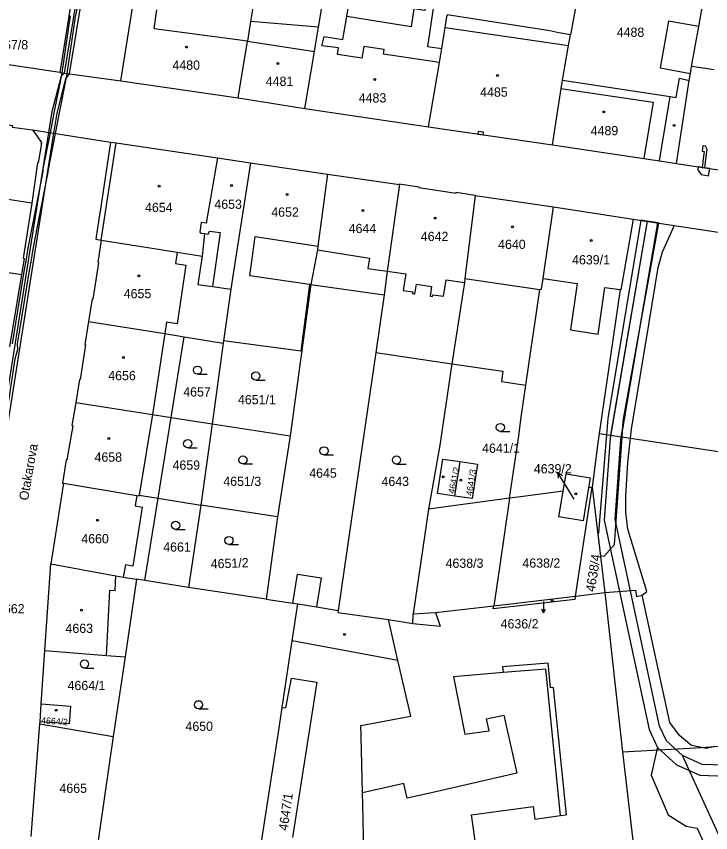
# Model space of a CAD drawing. Extents: x -756746 to -753363, y -1166406 to -1161727.
# Drawn here: x -755379 to -755251.5, y -1166014.7 to -1165864.8 of the extents above; entities that cross this region are included whole.
import ezdxf

# ---------------------------------------------------------------- set-up
doc = ezdxf.new("R2010")
doc.units = 0
for name, color, linetype in [('Hranice parcel', 7, 'Continuous'), ('Parcelní čísla', 7, 'Continuous'), ('Pop  PČ popisy', 7, 'Continuous'), ('Vnitřní kresba', 7, 'Continuous'), ('Věcná břemena k části', 7, 'Continuous'), ('Značky budov', 7, 'Continuous'), ('Značky kultur', 7, 'Continuous')]:
    doc.layers.add(name, color=color, linetype=linetype)

msp = doc.modelspace()

# ---------------------------------------------------------------- linework, layer by layer
at = {"layer": 'Hranice parcel'}
for p, q in [((-755333.64, -1165850.7), (-755336.01, -1165865.74)), ((-755323.54, -1165866.79), (-755322.25, -1165859.17)), ((-755359.86, -1165876.65), (-755357.62, -1165862.89)), ((-755336.01, -1165865.74), (-755336.58, -1165869.38)), ((-755323.54, -1165866.79), (-755336.01, -1165865.74)), ((-755338.26, -1165879.79), (-755336.58, -1165869.38)), ((-755371.06, -1165875.11), (-755390.26, -1165872.27)), ((-755371.06, -1165875.11), (-755359.86, -1165876.65)), ((-755359.86, -1165876.65), (-755338.26, -1165879.79)), ((-755257.81, -1165891.82), (-755255.48, -1165876.6)), ((-755338.26, -1165879.79), (-755326.03, -1165881.71)), ((-755326.03, -1165881.71), (-755303.36, -1165885.1)), ((-755376.04, -1165885.67), (-755361.71, -1165887.89)), ((-755303.36, -1165885.1), (-755280.55, -1165888.41)), ((-755342.06, -1165890.8), (-755336.05, -1165891.68)), ((-755336.05, -1165891.68), (-755321.86, -1165893.79)), ((-755321.86, -1165893.79), (-755308.67, -1165895.66)), ((-755294.79, -1165897.7), (-755280.39, -1165899.79)), ((-755280.39, -1165899.79), (-755265.76, -1165902.04)), ((-755324.96, -1165914.06), (-755328.74, -1165941.83)), ((-755324.96, -1165914.06), (-755311.47, -1165915.98)), ((-755339.65, -1165914.88), (-755340.98, -1165924.42)), ((-755311.47, -1165915.98), (-755313, -1165926.52)), ((-755350.58, -1165938.48), (-755348.19, -1165923.64)), ((-755348.19, -1165923.64), (-755341.04, -1165924.83)), ((-755340.98, -1165924.42), (-755341.04, -1165924.83)), ((-755341.04, -1165924.83), (-755343.04, -1165939.67)), ((-755313, -1165926.52), (-755299.07, -1165928.63)), ((-755353.01, -1165953.29), (-755350.58, -1165938.48)), ((-755350.58, -1165938.48), (-755343.04, -1165939.67)), ((-755343.04, -1165939.67), (-755345.12, -1165954.56)), ((-755343.04, -1165939.67), (-755328.74, -1165941.83)), ((-755328.74, -1165941.83), (-755331.04, -1165956.71)), ((-755298.51, -1165952.93), (-755297.54, -1165946.58)), ((-755370.37, -1165950.57), (-755372.69, -1165965.37)), ((-755276.37, -1165971.3), (-755273.28, -1165951.31)), ((-755273.28, -1165951.31), (-755273.93, -1165951.4)), ((-755273.28, -1165951.31), (-755270.93, -1165970.66)), ((-755355.41, -1165968.42), (-755353.01, -1165953.29)), ((-755353.01, -1165953.29), (-755345.12, -1165954.56)), ((-755345.12, -1165954.56), (-755347.4, -1165969.71)), ((-755331.04, -1165956.71), (-755345.12, -1165954.56)), ((-755288.46, -1165953.33), (-755303.33, -1165955.3)), ((-755303.33, -1165955.3), (-755306.13, -1165974.57)), ((-755331.04, -1165956.71), (-755333.14, -1165971.84)), ((-755373.77, -1165981.29), (-755372.69, -1165965.37)), ((-755356.97, -1165968.21), (-755359.07, -1165982.44)), ((-755355.41, -1165968.42), (-755356.97, -1165968.21)), ((-755347.4, -1165969.71), (-755355.41, -1165968.42)), ((-755333.14, -1165971.84), (-755347.4, -1165969.71)), ((-755276.37, -1165971.3), (-755270.93, -1165970.66)), ((-755270.93, -1165970.66), (-755267.71, -1165999.92)), ((-755276.46, -1165971.89), (-755291.44, -1165973.65)), ((-755291.35, -1165973.06), (-755276.37, -1165971.3)), ((-755276.37, -1165971.3), (-755276.46, -1165971.89)), ((-755291.44, -1165973.65), (-755291.35, -1165973.06)), ((-755374.44, -1165991.11), (-755373.77, -1165981.29)), ((-755359.07, -1165982.44), (-755361.23, -1165997.07)), ((-755374.67, -1165994.37), (-755374.44, -1165991.11)), ((-755376.29, -1166015.44), (-755374.69, -1165994.77)), ((-755374.69, -1165994.77), (-755374.67, -1165994.37)), ((-755374.69, -1165994.77), (-755361.23, -1165997.07)), ((-755267.71, -1165999.92), (-755264.63, -1166026.3))]:
    msp.add_line(p, q, dxfattribs=at)
for points in [[(-755298.59, -1165856.2), (-755301.27, -1165855.58), (-755301.84, -1165858.89), (-755302.48, -1165858.78), (-755303.01, -1165861.27), (-755303.67, -1165861.19), (-755303.83, -1165862.7), (-755304, -1165863.75), (-755306.02, -1165863.42), (-755306.55, -1165866.72), (-755318.35, -1165864.82), (-755317.54, -1165859.92), (-755322.25, -1165859.17)], [(-755275.08, -1165855.46), (-755276.29, -1165862.87), (-755277.26, -1165868.19)], [(-755368.38, -1165858.31), (-755369.41, -1165864.76), (-755371.06, -1165875.11)], [(-755255.48, -1165876.6), (-755255.24, -1165875.27), (-755255.01, -1165873.98), (-755253.7, -1165866.66), (-755252.4, -1165859.39)], [(-755336.58, -1165869.38), (-755353.72, -1165867.07), (-755353.25, -1165863.62)], [(-755303.36, -1165885.1), (-755301.3, -1165873.3), (-755300.89, -1165870.7), (-755300.29, -1165866.87), (-755299.91, -1165864.49)], [(-755277.26, -1165868.19), (-755279.38, -1165867.8), (-755281.03, -1165867.48), (-755299.91, -1165864.49)], [(-755326.03, -1165881.71), (-755324.3, -1165871.28), (-755324.11, -1165870.11), (-755323.54, -1165866.79)], [(-755278.71, -1165876.54), (-755277.6, -1165870.15), (-755277.26, -1165868.19)], [(-755280.55, -1165888.41), (-755278.97, -1165878.03), (-755278.71, -1165876.54)], [(-755278.71, -1165876.54), (-755258.97, -1165879.54), (-755257.86, -1165879.73), (-755257.25, -1165876.15), (-755255.48, -1165876.6)], [(-755388.14, -1165883.94), (-755384.43, -1165884.47), (-755384.38, -1165884.17), (-755379.73, -1165884.84), (-755379.78, -1165885.14), (-755376.04, -1165885.67)], [(-755376.04, -1165885.67), (-755374.39, -1165887.99), (-755374.55, -1165888.15), (-755374.42, -1165888.17), (-755374.99, -1165891.71), (-755375.14, -1165891.68), (-755376.2, -1165899.14)], [(-755361.71, -1165887.89), (-755363.52, -1165899.78), (-755364.11, -1165903.66), (-755364.42, -1165905.71), (-755363.44, -1165905.89)], [(-755361.71, -1165887.89), (-755360.68, -1165888.04), (-755342.06, -1165890.8)], [(-755280.55, -1165888.41), (-755263.78, -1165890.92), (-755260.9, -1165891.35), (-755257.81, -1165891.82)], [(-755342.06, -1165890.8), (-755344.19, -1165902.8), (-755345.11, -1165902.65), (-755345.35, -1165904.43), (-755345.07, -1165904.63), (-755344.47, -1165904.71), (-755344.89, -1165908.84)], [(-755336.05, -1165891.68), (-755339.22, -1165912.07), (-755339.65, -1165914.88)], [(-755257.81, -1165891.82), (-755254.21, -1165892.37), (-755234.75, -1165895.27)], [(-755321.86, -1165893.79), (-755323.65, -1165907.02), (-755323.75, -1165907.71), (-755324.96, -1165914.06)], [(-755308.67, -1165895.66), (-755310.9, -1165911.61), (-755311.47, -1165915.98)], [(-755308.67, -1165895.66), (-755308.66, -1165895.59), (-755305.1, -1165896.11), (-755305.12, -1165896.23), (-755298.26, -1165897.26), (-755298.24, -1165897.12), (-755294.78, -1165897.63), (-755294.79, -1165897.7)], [(-755376.2, -1165899.14), (-755384.18, -1165897.9), (-755387.74, -1165897.34), (-755388.9, -1165897.16), (-755390.02, -1165896.98)], [(-755376.2, -1165899.14), (-755377.75, -1165909.24), (-755377.6, -1165909.27), (-755378.06, -1165912.25)], [(-755294.79, -1165897.7), (-755296.65, -1165912.98), (-755296.74, -1165913.69), (-755299.07, -1165928.63)], [(-755285.47, -1165932.53), (-755284.49, -1165925.78), (-755283.64, -1165920.07), (-755282.88, -1165914.94), (-755282.59, -1165914.93), (-755282.3, -1165912.94), (-755280.39, -1165899.79)], [(-755265.76, -1165902.04), (-755268.04, -1165915.01), (-755268.14, -1165914.99), (-755271.99, -1165941.43)], [(-755265.76, -1165902.04), (-755258.2, -1165903.19), (-755226.15, -1165908.07)], [(-755363.44, -1165905.89), (-755364.08, -1165910.03), (-755363.96, -1165910.05), (-755365, -1165916.73), (-755365.13, -1165916.71), (-755365.78, -1165920.87)], [(-755363.44, -1165905.89), (-755352.55, -1165907.63), (-755349.49, -1165908.11), (-755344.89, -1165908.84)], [(-755378.06, -1165912.25), (-755391.46, -1165910.18), (-755397.87, -1165909.19)], [(-755344.89, -1165908.84), (-755345.68, -1165914.04), (-755342.99, -1165914.41), (-755339.65, -1165914.88)], [(-755378.06, -1165912.25), (-755380.27, -1165925.46), (-755380.4, -1165925.44)], [(-755324.96, -1165914.06), (-755325.18, -1165914.03), (-755326.81, -1165926.29), (-755340.98, -1165924.42)], [(-755365.78, -1165920.87), (-755366.45, -1165925.11), (-755366.31, -1165925.13), (-755367.31, -1165931.5), (-755367.45, -1165931.48), (-755368.11, -1165935.7)], [(-755365.78, -1165920.87), (-755351.76, -1165923.04), (-755348.19, -1165923.64)], [(-755313, -1165926.52), (-755315.26, -1165942.02), (-755317.58, -1165957.88), (-755319.95, -1165973.95)], [(-755299.07, -1165928.63), (-755301.24, -1165943.59), (-755303.33, -1165955.3)], [(-755299.07, -1165928.63), (-755289.66, -1165930), (-755289.94, -1165931.86), (-755285.47, -1165932.53)], [(-755288.46, -1165953.33), (-755286.83, -1165942.28), (-755286.3, -1165938.44), (-755285.47, -1165932.53)], [(-755368.11, -1165935.7), (-755368.82, -1165939.97), (-755368.67, -1165940), (-755369.73, -1165946.29), (-755369.86, -1165946.27), (-755370.57, -1165950.54), (-755370.37, -1165950.57)], [(-755368.11, -1165935.7), (-755354.01, -1165937.94), (-755350.58, -1165938.48)], [(-755271.99, -1165941.43), (-755272.23, -1165943.13), (-755273.28, -1165951.31)], [(-755271.99, -1165941.43), (-755266.24, -1165942.3), (-755231.88, -1165947.5)], [(-755298.51, -1165952.93), (-755301.71, -1165952.46), (-755300.72, -1165946.12), (-755297.54, -1165946.58)], [(-755297.54, -1165946.58), (-755294.36, -1165947.05), (-755295.31, -1165953.39), (-755298.51, -1165952.93)], [(-755278.61, -1165952.02), (-755278.07, -1165948.83), (-755273.62, -1165949.54), (-755273.93, -1165951.4)], [(-755370.37, -1165950.57), (-755356.91, -1165952.82), (-755356.47, -1165952.89), (-755356.45, -1165952.74), (-755353.01, -1165953.29)], [(-755273.93, -1165951.4), (-755274.94, -1165957.44), (-755279.4, -1165956.72), (-755278.61, -1165952.02)], [(-755278.61, -1165952.02), (-755286.45, -1165953.06), (-755288.46, -1165953.33)], [(-755288.46, -1165953.33), (-755290.32, -1165966.05), (-755291.35, -1165973.06)], [(-755372.69, -1165965.37), (-755360.76, -1165967.57), (-755359.38, -1165967.82), (-755356.97, -1165968.21)], [(-755333.14, -1165971.84), (-755328.28, -1165972.57), (-755327.36, -1165972.71)], [(-755335.36, -1166025.81), (-755334.11, -1166017.2), (-755332.76, -1166008.51), (-755330.85, -1165995.94), (-755330.23, -1165991.73), (-755328.39, -1165979.53), (-755327.36, -1165972.71)], [(-755327.36, -1165972.71), (-755323.93, -1165973.29), (-755319.95, -1165973.95)], [(-755319.95, -1165973.95), (-755320, -1165974.31), (-755310.67, -1165975.6)], [(-755306.13, -1165974.57), (-755302.05, -1165974.32), (-755291.35, -1165973.06)], [(-755315, -1166027.54), (-755315.21, -1166018.6), (-755315.42, -1166009.49), (-755315.47, -1166007.43), (-755315.72, -1165997.02), (-755315.75, -1165995.05), (-755306.6, -1165993.33), (-755308.94, -1165983.12), (-755310.67, -1165975.6)], [(-755310.67, -1165975.6), (-755306.22, -1165976.34), (-755306.13, -1165974.57)], [(-755373.77, -1165981.29), (-755362.46, -1165982.18), (-755359.07, -1165982.44)], [(-755374.44, -1165991.11), (-755369.07, -1165991.51), (-755369.3, -1165994.77), (-755374.67, -1165994.37)], [(-755361.23, -1165997.07), (-755362.04, -1166002.59), (-755364.7, -1166020.81)], [(-755267.71, -1165999.92), (-755253.23, -1165999.08), (-755250.82, -1165998.94), (-755233.62, -1165997.95)]]:
    msp.add_lwpolyline(points, dxfattribs=at)
at = {"layer": 'Pop  PČ popisy'}
for p, q in [((-755278.06, -1165951.08), (-755279.65, -1165948.53)), ((-755279.65, -1165948.53), (-755278.7, -1165949.12)), ((-755279.65, -1165948.53), (-755279.54, -1165949.65)), ((-755276.57, -1165953.49), (-755278.06, -1165951.08)), ((-755282.2, -1165972.27), (-755282.2, -1165974.37)), ((-755282.2, -1165974.37), (-755282.55, -1165973.67)), ((-755282.2, -1165974.37), (-755281.85, -1165973.67))]:
    msp.add_line(p, q, dxfattribs=at)
at = {"layer": 'Vnitřní kresba'}
for p, q in [((-755302.39, -1165862.93), (-755303.54, -1165870.34)), ((-755319.04, -1165869.03), (-755318.35, -1165864.82)), ((-755259.26, -1165865.66), (-755260.79, -1165874.27)), ((-755253.7, -1165866.66), (-755259.26, -1165865.66)), ((-755300.29, -1165866.87), (-755277.6, -1165870.15)), ((-755322.9, -1165870.24), (-755322.49, -1165868.47)), ((-755322.49, -1165868.47), (-755319.04, -1165869.03)), ((-755336.58, -1165869.38), (-755324.3, -1165871.28)), ((-755319.85, -1165870.57), (-755322.9, -1165870.24)), ((-755320.04, -1165871.83), (-755319.85, -1165870.57)), ((-755315.23, -1165870.34), (-755315.55, -1165872.48)), ((-755311.47, -1165870.9), (-755315.23, -1165870.34)), ((-755303.54, -1165870.34), (-755300.89, -1165870.7)), ((-755315.55, -1165872.48), (-755320.04, -1165871.83)), ((-755311.6, -1165871.77), (-755311.47, -1165870.9)), ((-755301.3, -1165873.3), (-755311.6, -1165871.77)), ((-755260.79, -1165874.27), (-755255.24, -1165875.27)), ((-755250.86, -1165874.61), (-755255.01, -1165873.98)), ((-755278.97, -1165878.03), (-755276.99, -1165878.33)), ((-755276.99, -1165878.33), (-755262.09, -1165880.57)), ((-755260.9, -1165891.35), (-755258.97, -1165879.54)), ((-755262.09, -1165880.57), (-755263.78, -1165890.92)), ((-755363.44, -1165905.89), (-755360.68, -1165888.04)), ((-755260.38, -1165908.07), (-755258.37, -1165903.58)), ((-755258.37, -1165903.58), (-755258.2, -1165903.19)), ((-755344.47, -1165904.71), (-755343.82, -1165904.79)), ((-755343.82, -1165904.79), (-755343.55, -1165904.25)), ((-755343.55, -1165904.25), (-755341.6, -1165904.53)), ((-755341.6, -1165904.53), (-755342.99, -1165914.41)), ((-755336.17, -1165912.47), (-755335.14, -1165905.25)), ((-755335.14, -1165905.25), (-755323.65, -1165907.02)), ((-755349.49, -1165908.11), (-755349.81, -1165910.18)), ((-755323.75, -1165907.71), (-755314.19, -1165909.21)), ((-755261.13, -1165910.91), (-755260.38, -1165908.07)), ((-755314.19, -1165909.21), (-755314.49, -1165911.11)), ((-755349.81, -1165910.18), (-755347.89, -1165910.47)), ((-755347.89, -1165910.47), (-755349.52, -1165921.26)), ((-755314.49, -1165911.11), (-755310.9, -1165911.61)), ((-755262.88, -1165921.38), (-755261.13, -1165910.91)), ((-755325.18, -1165914.03), (-755336.17, -1165912.47)), ((-755310.9, -1165911.61), (-755307.52, -1165912.1)), ((-755307.52, -1165912.1), (-755307.96, -1165915.13)), ((-755305.83, -1165915.8), (-755305.57, -1165914.01)), ((-755305.57, -1165914.01), (-755302.78, -1165914.42)), ((-755300.56, -1165916.21), (-755300.12, -1165913.18)), ((-755300.12, -1165913.18), (-755296.74, -1165913.69)), ((-755296.65, -1165912.98), (-755282.88, -1165914.94)), ((-755282.3, -1165912.94), (-755276.03, -1165913.87)), ((-755276.03, -1165913.87), (-755277.28, -1165922.4)), ((-755307.96, -1165915.13), (-755306.22, -1165915.39)), ((-755306.22, -1165915.39), (-755306.27, -1165915.73)), ((-755302.78, -1165914.42), (-755303.04, -1165916.2)), ((-755272.18, -1165923.15), (-755270.93, -1165914.61)), ((-755270.93, -1165914.61), (-755268.14, -1165914.99)), ((-755306.27, -1165915.73), (-755305.83, -1165915.8)), ((-755303.04, -1165916.2), (-755302.6, -1165916.27)), ((-755302.6, -1165916.27), (-755302.55, -1165915.92)), ((-755302.55, -1165915.92), (-755300.56, -1165916.21)), ((-755351.45, -1165920.97), (-755351.76, -1165923.04)), ((-755349.52, -1165921.26), (-755351.45, -1165920.97)), ((-755266.07, -1165940.65), (-755262.88, -1165921.38)), ((-755351.76, -1165923.04), (-755354.01, -1165937.94)), ((-755277.28, -1165922.4), (-755272.18, -1165923.15)), ((-755354.01, -1165937.94), (-755356.45, -1165952.74)), ((-755266.24, -1165942.3), (-755266.07, -1165940.65)), ((-755266.71, -1165946.76), (-755266.24, -1165942.3)), ((-755267.11, -1165952.94), (-755266.71, -1165946.76)), ((-755356.91, -1165952.82), (-755357.23, -1165954.74)), ((-755267.07, -1165955.89), (-755267.11, -1165952.94)), ((-755355.89, -1165954.96), (-755357.65, -1165965.8)), ((-755357.23, -1165954.74), (-755355.89, -1165954.96)), ((-755266.72, -1165958.99), (-755267.07, -1165955.89)), ((-755263.22, -1165970.46), (-755266.72, -1165958.99)), ((-755359.01, -1165965.57), (-755359.38, -1165967.82)), ((-755357.65, -1165965.8), (-755359.01, -1165965.57)), ((-755360.9, -1165970.27), (-755360.76, -1165967.57)), ((-755328.28, -1165972.57), (-755327.4, -1165967.27)), ((-755327.4, -1165967.27), (-755323.04, -1165967.95)), ((-755323.04, -1165967.95), (-755323.93, -1165973.29)), ((-755362.46, -1165982.18), (-755361.85, -1165970.22)), ((-755361.85, -1165970.22), (-755360.9, -1165970.27)), ((-755270.93, -1165970.66), (-755265.35, -1165970.2)), ((-755265.35, -1165970.2), (-755265.15, -1165971.35)), ((-755265.15, -1165971.35), (-755264.08, -1165971.13)), ((-755264.08, -1165971.13), (-755263.22, -1165970.46)), ((-755259.01, -1165994.54), (-755264.08, -1165971.13)), ((-755302.05, -1165974.32), (-755301.17, -1165976.81)), ((-755306.22, -1165976.34), (-755301.17, -1165976.81)), ((-755308.94, -1165983.12), (-755328.39, -1165979.53)), ((-755281.37, -1165983.59), (-755289.74, -1165984.31)), ((-755289.74, -1165984.31), (-755289.65, -1165985.35)), ((-755280.92, -1165988.12), (-755281.37, -1165983.59)), ((-755289.65, -1165985.35), (-755298.77, -1165986.11)), ((-755298.77, -1165986.11), (-755296.65, -1165996.65)), ((-755281.8, -1165984.69), (-755289.65, -1165985.35)), ((-755279.12, -1166011.6), (-755281.8, -1165984.69)), ((-755329.54, -1165991.83), (-755328.51, -1165986.38)), ((-755328.51, -1165986.38), (-755323.87, -1165987.08)), ((-755323.87, -1165987.08), (-755328.33, -1166015.66)), ((-755280.44, -1165988.07), (-755280.92, -1165988.12)), ((-755280.44, -1165988.07), (-755278.07, -1166011.46)), ((-755330.23, -1165991.73), (-755329.54, -1165991.83)), ((-755292.67, -1165993.84), (-755289.48, -1165993.15)), ((-755289.48, -1165993.15), (-755289, -1165995.36)), ((-755292.18, -1165996.06), (-755292.67, -1165993.84)), ((-755257.27, -1165996.88), (-755259.01, -1165994.54)), ((-755296.65, -1165996.65), (-755292.18, -1165996.06)), ((-755289, -1165995.36), (-755287.13, -1166003.83)), ((-755255.01, -1165998.74), (-755257.27, -1165996.88)), ((-755253.23, -1165999.08), (-755255.01, -1165998.74)), ((-755252.26, -1165999.27), (-755253.23, -1165999.08)), ((-755250.82, -1165998.94), (-755252.26, -1165999.27)), ((-755287.13, -1166003.83), (-755303.34, -1166007.54)), ((-755307.86, -1166005.71), (-755315.47, -1166007.43)), ((-755307.24, -1166008.42), (-755307.86, -1166005.71)), ((-755303.34, -1166007.54), (-755307.24, -1166008.42)), ((-755295.44, -1166011.5), (-755284.09, -1166009.96)), ((-755284.09, -1166009.96), (-755283.78, -1166012.24)), ((-755294.57, -1166017.52), (-755295.44, -1166011.5)), ((-755283.78, -1166012.24), (-755279.12, -1166011.6)), ((-755279.12, -1166011.6), (-755278.07, -1166011.46))]:
    msp.add_line(p, q, dxfattribs=at)
at = {"layer": 'Věcná břemena k části'}
for points in [[(-755363.63, -1165835.25), (-755370.22, -1165875.23), (-755370.82, -1165875.79), (-755372.53, -1165882.36), (-755373.13, -1165886.12), (-755385.09, -1165961.43)], [(-755384.09, -1165961.55), (-755372.14, -1165886.27), (-755371.55, -1165882.56), (-755369.92, -1165876.29), (-755369.26, -1165875.35), (-755362.57, -1165834.95)], [(-755385.7, -1165976), (-755385.24, -1165970.06), (-755385.09, -1165967.62), (-755384.74, -1165963.55), (-755384.22, -1165958.86), (-755383.1, -1165952.19), (-755382.24, -1165946.62), (-755380.28, -1165934.63), (-755379.25, -1165927.68), (-755378.78, -1165925.92), (-755378.82, -1165925), (-755376.67, -1165911.82), (-755376.32, -1165909.89), (-755375.93, -1165907.57), (-755373.96, -1165897.48), (-755373.19, -1165893.41), (-755373.15, -1165892.92), (-755371.85, -1165886.32), (-755371.15, -1165882.8), (-755369.79, -1165876), (-755369.69, -1165875.3), (-755368.15, -1165864.9), (-755367.31, -1165860.7)], [(-755369.13, -1165864.72), (-755370.67, -1165875.16), (-755370.77, -1165875.82), (-755372.13, -1165882.6), (-755372.84, -1165886.17), (-755374.15, -1165892.78), (-755374.19, -1165893.27), (-755374.9, -1165897.12), (-755376.91, -1165907.39), (-755377.3, -1165909.71), (-755377.65, -1165911.66), (-755379.82, -1165924.94)], [(-755249.05, -1166002.33), (-755253.05, -1166002.21), (-755256.71, -1166000.59), (-755259.65, -1165997.88), (-755260.89, -1165995.17), (-755269.06, -1165957.22), (-755267.99, -1165942.54), (-755261.22, -1165902.73), (-755263.19, -1165902.43), (-755269.98, -1165942.3), (-755271.07, -1165957.36), (-755262.8, -1165995.81), (-755261.3, -1165999.08), (-755257.82, -1166002.28), (-755253.5, -1166004.19), (-755248.65, -1166004.34)]]:
    msp.add_lwpolyline(points, dxfattribs=at)
for points in [[(-755294.29, -1165886.42), (-755293.31, -1165886.56), (-755293.23, -1165886.08), (-755294.21, -1165885.92)], [(-755252.47, -1165888.63), (-755252.96, -1165888.56), (-755253.11, -1165889.55), (-755252.73, -1165889.6), (-755252.86, -1165890.5), (-755253.09, -1165892.54), (-755252.6, -1165892.61), (-755252.36, -1165890.56), (-755252.17, -1165889.23)], [(-755252.6, -1165892.61), (-755253.09, -1165892.54), (-755253.83, -1165892.43), (-755253.9, -1165893), (-755253.26, -1165893.84), (-755251.92, -1165894.07), (-755251.69, -1165892.75)], [(-755272.1, -1165959.65), (-755272.24, -1165959.84), (-755271.75, -1165963.93), (-755271.01, -1165963.87), (-755269.17, -1165961.81), (-755267.79, -1165942.07), (-755267.58, -1165939.08), (-755261.02, -1165902.76), (-755264.37, -1165902.25), (-755270.41, -1165938.65), (-755270.65, -1165941.63)], [(-755267.91, -1165942.05), (-755261.22, -1165902.73), (-755263.19, -1165902.43), (-755269.89, -1165941.75), (-755269.98, -1165942.3), (-755271.07, -1165957.36), (-755262.8, -1165995.81), (-755261.3, -1165999.08), (-755261.41, -1165999.55), (-755262.47, -1166004.18), (-755259.32, -1166011.48), (-755255.99, -1166013.56), (-755253.98, -1166013.91), (-755249.46, -1166023.94), (-755246.26, -1166023.44), (-755247.54, -1166020.64), (-755256.71, -1166000.59), (-755258.05, -1165999.36), (-755259.65, -1165997.88), (-755260.89, -1165995.17), (-755269.06, -1165957.22), (-755267.99, -1165942.54)]]:
    msp.add_lwpolyline(points, close=True, dxfattribs=at)
at = {"layer": 'Značky budov'}
for centre in [(-755347.75, -1165870.43), (-755330.98, -1165873.45), (-755313.22, -1165876.41), (-755290.66, -1165875.64), (-755271.13, -1165882.36), (-755258.23, -1165884.82), (-755352.8, -1165895.98), (-755339.5, -1165895.88), (-755329.32, -1165897.51), (-755315.39, -1165900.44), (-755302.1, -1165901.84), (-755287.9, -1165903.46), (-755273.44, -1165905.96), (-755356.55, -1165912.46), (-755359.37, -1165927.46), (-755362.05, -1165942.33), (-755300.62, -1165949.39), (-755297.41, -1165949.99), (-755276.26, -1165952.52), (-755364.1, -1165957.37), (-755280.63, -1165972.14), (-755367.07, -1165973.86), (-755318.74, -1165978.32), (-755371.73, -1165992.27)]:
    msp.add_circle(centre, 0.175, dxfattribs=at)
at = {"layer": 'Značky kultur'}
for p, q in [((-755345.76, -1165930.54), (-755344.01, -1165930.54)), ((-755335.06, -1165931.62), (-755333.31, -1165931.62)), ((-755290.13, -1165941.06), (-755288.38, -1165941.06)), ((-755347.55, -1165944.05), (-755345.8, -1165944.05)), ((-755322.52, -1165945.36), (-755320.77, -1165945.36)), ((-755337.42, -1165947.02), (-755335.67, -1165947.02)), ((-755309.21, -1165947.03), (-755307.46, -1165947.03)), ((-755349.78, -1165959.04), (-755348.03, -1165959.04)), ((-755339.99, -1165961.83), (-755338.24, -1165961.83)), ((-755366.52, -1165984.5), (-755364.77, -1165984.5)), ((-755345.58, -1165992), (-755343.83, -1165992))]:
    msp.add_line(p, q, dxfattribs=at)
for centre in [(-755345.76, -1165929.79), (-755335.06, -1165930.87), (-755290.13, -1165940.31), (-755347.55, -1165943.3), (-755322.52, -1165944.61), (-755337.42, -1165946.27), (-755309.21, -1165946.28), (-755349.78, -1165958.29), (-755339.99, -1165961.08), (-755366.52, -1165983.75), (-755345.58, -1165991.25)]:
    msp.add_circle(centre, 0.75, dxfattribs=at)

# ---------------------------------------------------------------- texts
at = {"layer": 'Parcelní čísla'}
for s, p in [('4488', (-755268.77, -1165868.56)), ('4467/8', (-755383.82, -1165870.86)), ('4480', (-755350.36, -1165874.6)), ('4481', (-755333.22, -1165877.57)), ('4485', (-755293.85, -1165879.56)), ('4483', (-755316.15, -1165880.62)), ('4489', (-755273.55, -1165886.64)), ('4654', (-755355.39, -1165900.75)), ('4653', (-755342.66, -1165900.15)), ('4652', (-755332.21, -1165901.6)), ('4644', (-755317.99, -1165904.61)), ('4642', (-755304.75, -1165906.07)), ('4640', (-755290.55, -1165907.52)), ('4639/1', (-755276.97, -1165910.36)), ('4655', (-755359.3, -1165916.57)), ('4656', (-755362.15, -1165931.63)), ('4657', (-755348.38, -1165934.63)), ('4651/1', (-755338.33, -1165936.05)), ('4641/1', (-755293.49, -1165944.97)), ('4658', (-755364.67, -1165946.61)), ('4659', (-755350.34, -1165948.08)), ('4639/2', (-755283.99, -1165948.75)), ('4645', (-755325.24, -1165949.55)), ('4651/3', (-755341.02, -1165951.05)), ('4643', (-755311.97, -1165951.07)), ('4660', (-755367.1, -1165961.59)), ('4661', (-755352.05, -1165963.12)), ('4638/3', (-755300.2, -1165966.1)), ('4638/2', (-755286.09, -1165966.07)), ('4662', (-755382.57, -1165974.46)), ('4636/2', (-755290.09, -1165977.23)), ('4663', (-755370, -1165978.06)), ('4664/1', (-755369.62, -1165988.56)), ('4650', (-755347.97, -1165996.04)), ('4665', (-755371.11, -1166007.43))]:
    msp.add_text(s, height=1.7, dxfattribs=at).set_placement(p)
for s, height, rotation, p in [('4641/2', 1.2, 78, (-755298.57, -1165952.55)), ('4641/3', 1.2, 81, (-755295.31, -1165952.93)), ('4651/2', 1.7, 2, (-755343.3, -1165966.23)), ('4638/4', 1.7, 81, (-755272.81, -1165970.6)), ('4664/2', 1.2, 356, (-755374.49, -1165994.69)), ('4647/1', 1.7, 82, (-755329.2, -1166014.46))]:
    msp.add_text(s, height=height, rotation=rotation, dxfattribs=at).set_placement(p)
at = {"layer": 'Pop  PČ popisy'}
msp.add_text('Otakarova', height=1.7, rotation=80, dxfattribs=at).set_placement((-755376.89, -1165953.81))

doc.saveas('drawing.dxf')
